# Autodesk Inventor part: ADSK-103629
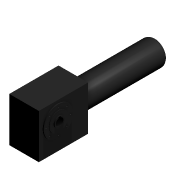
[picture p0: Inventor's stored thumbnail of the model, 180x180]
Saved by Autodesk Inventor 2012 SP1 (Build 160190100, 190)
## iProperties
Shininess: 0.0
Created: 2000-10
Part Number: ADSK-103629
Checked By: PT
Description: SK9032AF; Bore U=2", H3-A, c/w 1.5 HP DC Motor
Document SubType Name: Modeling
Designer: Administrator
Stock Number: ADSK-103629
Density: 1 g/cm^3
Material: Default
Density: 0.0
Volumn: 0.0
Area: 0.0
PropertySet Name: Model Information
Control State: 0
Master: False
Checked Out: False
Author: Administrator
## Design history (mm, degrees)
node "Extrusion1" dims "d2" = 332.994, "d3" = 0
  sketch "Sketch1"
    geometry: L1 (-39.031, 272.14)-(160.867, 272.14); L2 (160.867, 272.14)-(160.867, -27.834); L3 (160.867, -27.834)-(-39.031, -27.834); L4 (-39.031, -27.834)-(-39.031, 272.14)
    constraints: 8 end point, 2 parallel, 1 horizontal, 1 perpendicular
    dimensions: "d0" = 299.974 distance of L3.end L1.start; "d1" = 199.898 distance of L2.end L3.end
node "Extrusion2" dims "d5" = 6.35, "d6" = 0
  sketch "Sketch2"
    geometry: L1 (-332.994, 299.974)-(-332.994, 0) reference; L2 (0, 0)-(-332.994, 0) reference; C1 r 99.949 at (-207.01, 180.086)
    constraints: 1 centre point
    dimensions: "d4" = 199.898 diameter of C1; "d38" = 125.984 distance from line of L1 C1.centre; "d39" = 180.086 distance from line of L2 C1.centre
node "Extrusion7" dims "d24" = 558.8, "d25" = 0
  sketch "Sketch7"
    geometry: L1 (39.031, 272.14)-(39.031, -27.834) reference; L2 (-160.867, -27.834)-(-160.867, 272.14) reference; L3 (-292.655, 152.252)-(64.545, 152.252) reference; C1 r 82.55 at (-60.918, 128.376)
    constraints: 1 centre point
    dimensions: "d20" = 99.949 distance from line of L2 C1.centre; "d21" = 99.949 distance from line of L1 C1.centre (derived); "d22" = 165.1 diameter of C1; "d23" = 23.876 distance from line of L3 C1.centre
node "Fillet1" dims "d26" = 25.4
workplane "Work Plane1"
node "Extrusion10" dims "d49" = 3.048, "d50" = 0
  sketch "Sketch11"
    geometry: C1 r 99.949 at (0, 0) reference; C2 r 64.999 at (0, 0)
    constraints: 1 centre point
    dimensions: "d48" = 129.9972 diameter of C2
node "Extrusion11" dims "d51" = 6.35, "d52" = 0
  sketch "Sketch12"
    geometry: C1 r 99.949 at (207.01, 180.086) reference
node "Extrusion12" dims "d53" = 3.048, "d54" = 0
  sketch "Sketch13"
    geometry: C1 r 64.999 at (0, 0) reference
node "Extrusion13" dims "d56" = 3.048, "d57" = 0
  sketch "Sketch14"
    geometry: C1 r 64.999 at (0, 0) reference; C2 r 25.4 at (0, 0)
    constraints: 1 centre point
    dimensions: "d55" = 50.8 diameter of C2
node "Hole2" dims "d64" = 8.376, "d65" = 9.525, "d66" = 6.35, "d67" = 60 deg, "d68" = 19.05, "d69" = 118 deg, "d83" = 12.7
  sketch "Sketch16" dims "d63" = 165.1
    geometry: L1 (0, 0)-(0, 165.1); C1 r 99.949 at (0, 0) reference; 1 further point
    constraints: 2 end point, 1 midpoint, 1 vertical, 1 vertical alignment, 2 other
node "Circular Pattern2" dims "d70" = 80, "d72" = 45 deg
node "Extrusion15" dims "d74" = 5.08, "d75" = 0
  sketch "Sketch17"
    geometry: C1 r 25.4 at (0, 0) reference; C2 r 35.052 at (0, 0)
    constraints: 1 centre point
    dimensions: "d73" = 70.104 diameter of C2
node "Extrusion16" dims "d76" = 5.08, "d77" = 0
  sketch "Sketch18"
    geometry: C1 r 25.4 at (0, 0) reference; C2 r 35.052 at (0, 0) reference
node "Extrusion17" dims "d81" = 5.08, "d82" = 0
  sketch "Sketch19"
    geometry: L1 (-6.35, 24.593)-(6.35, 24.593); L2 (6.35, 24.593)-(6.35, 30.943); L3 (6.35, 30.943)-(-6.35, 30.943); L4 (-6.35, 30.943)-(-6.35, 24.593); 1 further point
    constraints: 8 end point, 2 parallel, 1 horizontal, 1 perpendicular, 2 other
    dimensions: "d78" = 6.35 distance from line of point (0, 0) L4 (= 0.5 x d79); "d79" = 12.7 distance of L2.end L3.end; "d80" = 6.35 distance of L3.end L1.start (= d78)
body "Solid1"
other parameters: "d40" = 50.8
